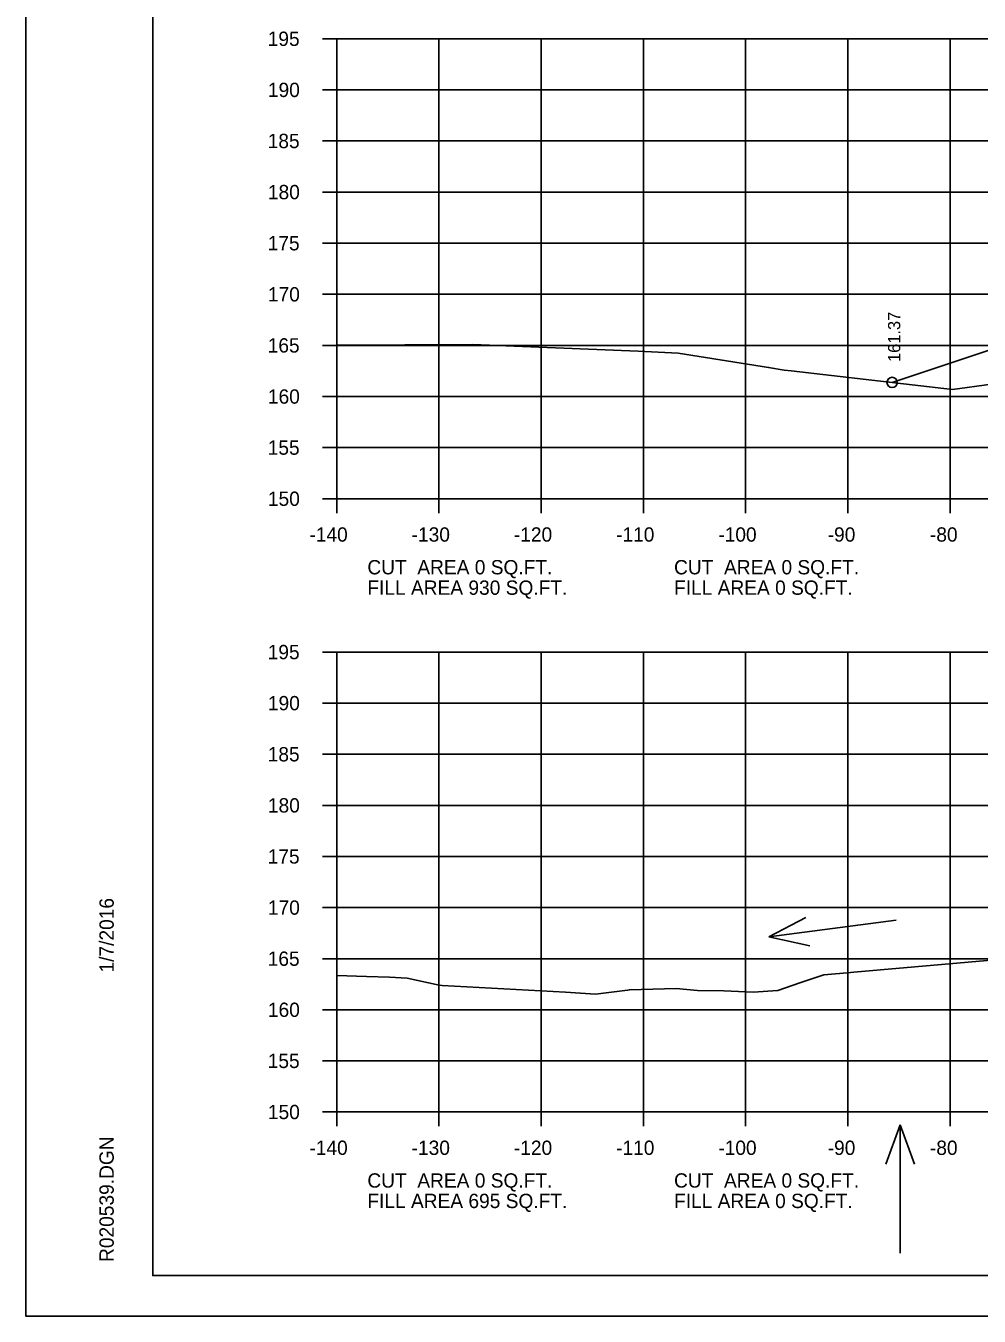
# Model space of a CAD drawing. Extents: x 915787 to 919910, y 133456 to 136717.
# Drawn here: x 916243.6 to 916336.8, y 134522.7 to 134649 of the extents above; entities that cross this region are included whole.
import ezdxf

# ---------------------------------------------------------------- set-up
doc = ezdxf.new("R2010")
doc.units = 0
for name, color, linetype in [('R_Axis', 7, 'Continuous'), ('R_Axis Annot', 7, 'Continuous'), ('R_Border', 7, 'Continuous'), ('R_Border Notes', 7, 'Continuous'), ('R_Exist Surface', 7, 'Continuous'), ('R_Fin Surface', 7, 'Continuous'), ('R_Grid', 7, 'Continuous'), ('R_No Plot', 7, 'Continuous'), ('R_Water Annot', 7, 'Continuous'), ('R_Xsect Elev', 7, 'Continuous')]:
    doc.layers.add(name, color=color, linetype=linetype)

msp = doc.modelspace()

# ---------------------------------------------------------------- linework, layer by layer
at = {"layer": 'R_Axis'}
for p, q in [((916272.58, 134647.7), (916273.98, 134647.7)), ((916273.98, 134602.7), (916273.98, 134647.7)), ((916272.58, 134642.7), (916273.98, 134642.7)), ((916272.58, 134637.7), (916273.98, 134637.7)), ((916272.58, 134632.7), (916273.98, 134632.7)), ((916272.58, 134627.7), (916273.98, 134627.7)), ((916272.58, 134622.7), (916273.98, 134622.7)), ((916272.58, 134617.7), (916273.98, 134617.7)), ((916272.58, 134612.7), (916273.98, 134612.7)), ((916272.58, 134607.7), (916273.98, 134607.7)), ((916272.58, 134602.7), (916273.98, 134602.7)), ((916273.98, 134602.7), (916553.98, 134602.7)), ((916273.98, 134601.3), (916273.98, 134602.7)), ((916283.98, 134601.3), (916283.98, 134602.7)), ((916293.98, 134601.3), (916293.98, 134602.7)), ((916303.98, 134601.3), (916303.98, 134602.7)), ((916313.98, 134601.3), (916313.98, 134602.7)), ((916323.98, 134601.3), (916323.98, 134602.7)), ((916333.98, 134601.3), (916333.98, 134602.7)), ((916272.58, 134587.7), (916273.98, 134587.7)), ((916273.98, 134542.7), (916273.98, 134587.7)), ((916272.58, 134582.7), (916273.98, 134582.7)), ((916272.58, 134577.7), (916273.98, 134577.7)), ((916272.58, 134572.7), (916273.98, 134572.7)), ((916272.58, 134567.7), (916273.98, 134567.7)), ((916272.58, 134562.7), (916273.98, 134562.7)), ((916272.58, 134557.7), (916273.98, 134557.7)), ((916272.58, 134552.7), (916273.98, 134552.7)), ((916272.58, 134547.7), (916273.98, 134547.7)), ((916272.58, 134542.7), (916273.98, 134542.7)), ((916273.98, 134542.7), (916553.98, 134542.7)), ((916273.98, 134541.3), (916273.98, 134542.7)), ((916283.98, 134541.3), (916283.98, 134542.7)), ((916293.98, 134541.3), (916293.98, 134542.7)), ((916303.98, 134541.3), (916303.98, 134542.7)), ((916313.98, 134541.3), (916313.98, 134542.7)), ((916323.98, 134541.3), (916323.98, 134542.7)), ((916333.98, 134541.3), (916333.98, 134542.7))]:
    msp.add_line(p, q, dxfattribs=at)
at = {"layer": 'R_Border'}
for p, q in [((916255.98, 134526.7), (916255.98, 134732.16)), ((916255.98, 134526.7), (916255.98, 134526.7)), ((916572.16, 134526.7), (916255.98, 134526.7))]:
    msp.add_line(p, q, dxfattribs=at)
at = {"layer": 'R_Exist Surface'}
for points in [[(916273.98, 134617.72), (916287.3, 134617.79), (916303.46, 134617.13), (916307.38, 134616.95), (916316.23, 134615.55), (916317.75, 134615.29), (916318.43, 134615.21), (916334.22, 134613.4), (916338.02, 134613.91)], [(916273.98, 134556.06), (916276.89, 134555.95), (916279.15, 134555.88), (916280.86, 134555.8), (916283.99, 134555.1), (916284.31, 134555.07), (916296.35, 134554.42), (916299.3, 134554.23), (916302.15, 134554.6), (916302.47, 134554.63), (916302.61, 134554.66), (916307.19, 134554.79), (916309.26, 134554.6), (916311.86, 134554.57), (916314.72, 134554.42), (916317.14, 134554.59), (916319.27, 134555.34), (916321.62, 134556.12), (916323.91, 134556.3), (916324.58, 134556.38), (916390.57, 134562.15)]]:
    msp.add_lwpolyline(points, dxfattribs=at)
at = {"layer": 'R_Fin Surface'}
msp.add_lwpolyline([(916328.31, 134614.08), (916382.97, 134632.3), (916387.04, 134633.32), (916391.47, 134634.42), (916402.97, 134634.88), (916413.97, 134635.1), (916424.97, 134634.88), (916436.47, 134634.65), (916440.46, 134633.32), (916444.97, 134631.82), (916445.23, 134631.82)], dxfattribs=at)
at = {"layer": 'R_Grid'}
for p, q in [((916273.98, 134647.7), (916553.98, 134647.7)), ((916273.98, 134602.7), (916273.98, 134647.7)), ((916283.98, 134602.7), (916283.98, 134647.7)), ((916293.98, 134602.7), (916293.98, 134647.7)), ((916303.98, 134602.7), (916303.98, 134647.7)), ((916313.98, 134602.7), (916313.98, 134647.7)), ((916323.98, 134602.7), (916323.98, 134647.7)), ((916333.98, 134602.7), (916333.98, 134647.7)), ((916273.98, 134642.7), (916553.98, 134642.7)), ((916273.98, 134637.7), (916553.98, 134637.7)), ((916273.98, 134632.7), (916553.98, 134632.7)), ((916273.98, 134627.7), (916553.98, 134627.7)), ((916273.98, 134622.7), (916553.98, 134622.7)), ((916273.98, 134617.7), (916553.98, 134617.7)), ((916273.98, 134612.7), (916553.98, 134612.7)), ((916273.98, 134607.7), (916553.98, 134607.7)), ((916273.98, 134602.7), (916553.98, 134602.7)), ((916273.98, 134587.7), (916553.98, 134587.7)), ((916273.98, 134542.7), (916273.98, 134587.7)), ((916283.98, 134542.7), (916283.98, 134587.7)), ((916293.98, 134542.7), (916293.98, 134587.7)), ((916303.98, 134542.7), (916303.98, 134587.7)), ((916313.98, 134542.7), (916313.98, 134587.7)), ((916323.98, 134542.7), (916323.98, 134587.7)), ((916333.98, 134542.7), (916333.98, 134587.7)), ((916273.98, 134582.7), (916553.98, 134582.7)), ((916273.98, 134577.7), (916553.98, 134577.7)), ((916273.98, 134572.7), (916553.98, 134572.7)), ((916273.98, 134567.7), (916553.98, 134567.7)), ((916273.98, 134562.7), (916553.98, 134562.7)), ((916273.98, 134557.7), (916553.98, 134557.7)), ((916273.98, 134552.7), (916553.98, 134552.7)), ((916273.98, 134547.7), (916553.98, 134547.7)), ((916273.98, 134542.7), (916553.98, 134542.7))]:
    msp.add_line(p, q, dxfattribs=at)
at = {"layer": 'R_No Plot'}
msp.add_line((916243.57, 134522.73), (916576.91, 134522.73), dxfattribs=at)
for points in [[(916243.57, 134736.06), (916576.91, 134736.06), (916576.91, 134522.72), (916243.57, 134522.72)], [(916489.9, 134732.16), (916489.9, 134722.28), (916525.63, 134722.28), (916525.63, 134719.36), (916548.83, 134719.36), (916548.83, 134696.15), (916572.16, 134696.15), (916572.16, 134526.7), (916255.98, 134526.7), (916255.98, 134732.16)]]:
    msp.add_lwpolyline(points, close=True, dxfattribs=at)
msp.add_circle((916328.31, 134614.08), 0.5, dxfattribs=at)
msp.add_circle((916328.31, 134614.08), 0.5, dxfattribs=at)
at = {"layer": 'R_Water Annot'}
for p, q in [((916316.25, 134559.84), (916319.88, 134561.73)), ((916328.71, 134561.47), (916316.25, 134559.84)), ((916316.25, 134559.84), (916320.25, 134558.95)), ((916329.11, 134541.46), (916327.71, 134537.61)), ((916329.11, 134528.89), (916329.11, 134541.46)), ((916329.11, 134541.46), (916330.51, 134537.61))]:
    msp.add_line(p, q, dxfattribs=at)

# ---------------------------------------------------------------- texts
at = {"layer": 'R_Axis Annot'}
for s, p in [('195', (916267.23, 134647)), ('190', (916267.25, 134642)), ('185', (916267.23, 134637)), ('180', (916267.25, 134632)), ('175', (916267.23, 134627)), ('170', (916267.25, 134622)), ('165', (916267.23, 134617)), ('160', (916267.25, 134612)), ('155', (916267.23, 134607)), ('150', (916267.25, 134602)), ('-140', (916271.31, 134598.5)), ('-130', (916281.31, 134598.5)), ('-120', (916291.31, 134598.5)), ('-110', (916301.31, 134598.5)), ('-100', (916311.31, 134598.5)), ('-90', (916322.01, 134598.5)), ('-80', (916332.01, 134598.5)), ('195', (916267.23, 134587)), ('190', (916267.25, 134582)), ('185', (916267.23, 134577)), ('180', (916267.25, 134572)), ('175', (916267.23, 134567)), ('170', (916267.25, 134562)), ('165', (916267.23, 134557)), ('160', (916267.25, 134552)), ('155', (916267.23, 134547)), ('150', (916267.25, 134542)), ('-140', (916271.31, 134538.5)), ('-130', (916281.31, 134538.5)), ('-120', (916291.31, 134538.5)), ('-110', (916301.31, 134538.5)), ('-100', (916311.31, 134538.5)), ('-90', (916322.01, 134538.5)), ('-80', (916332.01, 134538.5))]:
    msp.add_text(s, height=1.4, dxfattribs=at).set_placement(p)
at = {"layer": 'R_Border'}
for s, p in [('1/7/2016', (916252.17, 134556.35)), ('R020539.DGN', (916252.17, 134528.03))]:
    msp.add_text(s, height=1.4, rotation=90, dxfattribs=at).set_placement(p)
at = {"layer": 'R_Border Notes'}
for s, p in [('CUT  AREA 0 SQ.FT.', (916276.98, 134595.3)), ('CUT  AREA 0 SQ.FT.', (916306.98, 134595.3)), ('FILL AREA 930 SQ.FT.', (916276.98, 134593.3)), ('FILL AREA 0 SQ.FT.', (916306.98, 134593.3)), ('CUT  AREA 0 SQ.FT.', (916276.98, 134535.3)), ('CUT  AREA 0 SQ.FT.', (916306.98, 134535.3)), ('FILL AREA 695 SQ.FT.', (916276.98, 134533.3)), ('FILL AREA 0 SQ.FT.', (916306.98, 134533.3))]:
    msp.add_text(s, height=1.4, dxfattribs=at).set_placement(p)
at = {"layer": 'R_Xsect Elev'}
msp.add_text('161.37', height=1.2, rotation=90, dxfattribs=at).set_placement((916329.11, 134616.08))

doc.saveas('drawing.dxf')
